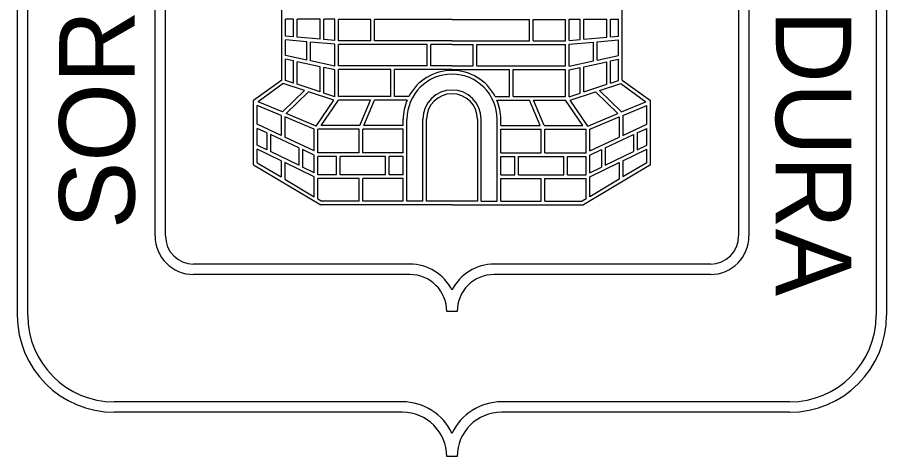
# Model space of a CAD drawing. Extents: x 0.2 to 61.3, y -17.9 to -0.8.
# Drawn here: x 33.86 to 43.86, y -17.88 to -12.82 of the extents above; entities that cross this region are included whole.
import ezdxf

# ---------------------------------------------------------------- set-up
doc = ezdxf.new("R2010")
doc.units = 0
doc.layers.add('Nivel 1', color=7, linetype='Continuous')
doc.layers.add('texto', color=7, linetype='Continuous')

msp = doc.modelspace()

# ---------------------------------------------------------------- linework, layer by layer
at = {"layer": 'Nivel 1'}
for p, q in [((33.86, -16.25), (33.86, -5.551)), ((43.86, -5.551), (43.86, -16.25)), ((33.979, -16.25), (33.979, -5.67)), ((43.741, -5.67), (43.741, -16.25)), ((35.444, -15.338), (35.444, -7.135)), ((42.276, -7.135), (42.276, -15.338)), ((35.563, -15.338), (35.563, -7.254)), ((42.157, -7.254), (42.157, -15.338)), ((36.901, -13.544), (36.901, -11.965)), ((40.819, -13.544), (40.819, -11.965)), ((37.035, -12.844), (36.943, -12.844)), ((36.943, -13.04), (36.943, -12.844)), ((37.035, -13.048), (37.035, -12.844)), ((37.342, -12.844), (37.077, -12.844)), ((37.077, -13.052), (37.077, -12.844)), ((37.342, -13.075), (37.342, -12.844)), ((37.512, -12.844), (37.385, -12.844)), ((37.385, -13.079), (37.385, -12.844)), ((37.512, -13.09), (37.512, -12.844)), ((37.927, -12.846), (37.554, -12.846)), ((37.554, -13.093), (37.554, -12.846)), ((37.927, -13.093), (37.927, -12.846)), ((38.86, -12.846), (37.97, -12.846)), ((37.97, -13.093), (37.97, -12.846)), ((38.86, -12.846), (39.75, -12.846)), ((39.75, -13.093), (39.75, -12.846)), ((39.792, -12.846), (40.165, -12.846)), ((39.792, -13.093), (39.792, -12.846)), ((40.165, -13.093), (40.165, -12.846)), ((40.208, -13.09), (40.208, -12.844)), ((40.208, -12.844), (40.335, -12.844)), ((40.335, -13.079), (40.335, -12.844)), ((40.377, -13.075), (40.377, -12.844)), ((40.377, -12.844), (40.642, -12.844)), ((40.642, -13.052), (40.642, -12.844)), ((40.685, -12.844), (40.776, -12.844)), ((40.685, -13.048), (40.685, -12.844)), ((40.776, -13.04), (40.776, -12.844)), ((37.035, -13.048), (36.943, -13.04)), ((36.943, -13.26), (36.943, -13.082)), ((37.191, -13.104), (36.943, -13.082)), ((37.342, -13.075), (37.077, -13.052)), ((37.512, -13.09), (37.385, -13.079)), ((37.927, -13.093), (37.554, -13.093)), ((38.86, -13.093), (37.97, -13.093)), ((38.86, -13.093), (39.75, -13.093)), ((39.792, -13.093), (40.165, -13.093)), ((40.208, -13.09), (40.335, -13.079)), ((40.377, -13.075), (40.642, -13.052)), ((40.529, -13.104), (40.776, -13.082)), ((40.685, -13.048), (40.776, -13.04)), ((40.776, -13.26), (40.776, -13.082)), ((37.191, -13.314), (37.191, -13.104)), ((37.233, -13.323), (37.233, -13.108)), ((37.512, -13.133), (37.233, -13.108)), ((37.512, -13.384), (37.512, -13.133)), ((38.576, -13.136), (37.554, -13.136)), ((37.554, -13.38), (37.554, -13.136)), ((38.576, -13.38), (38.576, -13.136)), ((38.86, -13.136), (38.618, -13.136)), ((38.618, -13.38), (38.618, -13.136)), ((38.86, -13.136), (39.102, -13.136)), ((39.102, -13.38), (39.102, -13.136)), ((39.144, -13.136), (40.165, -13.136)), ((39.144, -13.38), (39.144, -13.136)), ((40.165, -13.38), (40.165, -13.136)), ((40.208, -13.133), (40.486, -13.108)), ((40.208, -13.384), (40.208, -13.133)), ((40.486, -13.323), (40.486, -13.108)), ((40.529, -13.314), (40.529, -13.104)), ((37.191, -13.314), (36.943, -13.26)), ((40.529, -13.314), (40.776, -13.26)), ((37.035, -13.324), (36.943, -13.304)), ((36.943, -13.549), (36.943, -13.304)), ((37.035, -13.579), (37.035, -13.324)), ((37.342, -13.391), (37.077, -13.333)), ((37.077, -13.593), (37.077, -13.333)), ((37.512, -13.384), (37.233, -13.323)), ((37.342, -13.68), (37.342, -13.391)), ((37.512, -13.427), (37.385, -13.4)), ((37.385, -13.694), (37.385, -13.4)), ((38.576, -13.38), (37.554, -13.38)), ((38.86, -13.38), (38.618, -13.38)), ((38.86, -13.38), (39.102, -13.38)), ((39.144, -13.38), (40.165, -13.38)), ((40.208, -13.384), (40.486, -13.323)), ((40.208, -13.427), (40.335, -13.4)), ((40.335, -13.694), (40.335, -13.4)), ((40.377, -13.391), (40.642, -13.333)), ((40.377, -13.68), (40.377, -13.391)), ((40.642, -13.593), (40.642, -13.333)), ((40.685, -13.324), (40.776, -13.304)), ((40.685, -13.579), (40.685, -13.324)), ((40.776, -13.549), (40.776, -13.304)), ((37.512, -13.736), (37.512, -13.427)), ((38.157, -13.422), (37.554, -13.422)), ((37.554, -13.732), (37.554, -13.422)), ((38.157, -13.732), (38.157, -13.422)), ((38.86, -13.422), (38.2, -13.422)), ((38.2, -13.732), (38.2, -13.422)), ((38.86, -13.422), (39.52, -13.422)), ((39.52, -13.732), (39.52, -13.422)), ((39.562, -13.422), (40.165, -13.422)), ((39.562, -13.732), (39.562, -13.422)), ((40.165, -13.732), (40.165, -13.422)), ((40.208, -13.736), (40.208, -13.427)), ((36.901, -13.544), (36.577, -13.778)), ((36.917, -13.585), (36.628, -13.793)), ((37.163, -13.666), (36.917, -13.585)), ((37.035, -13.579), (36.943, -13.549)), ((37.342, -13.68), (37.077, -13.593)), ((40.377, -13.68), (40.642, -13.593)), ((40.556, -13.666), (40.803, -13.585)), ((40.685, -13.579), (40.776, -13.549)), ((40.803, -13.585), (41.091, -13.793)), ((40.819, -13.544), (41.142, -13.778)), ((36.909, -13.911), (37.163, -13.666)), ((36.951, -13.929), (37.209, -13.681)), ((37.501, -13.777), (37.209, -13.681)), ((37.512, -13.736), (37.385, -13.694)), ((40.208, -13.736), (40.335, -13.694)), ((40.219, -13.777), (40.511, -13.681)), ((40.768, -13.929), (40.511, -13.681)), ((40.811, -13.911), (40.556, -13.666)), ((36.577, -14.519), (36.577, -13.778)), ((36.909, -13.911), (36.628, -13.793)), ((37.298, -14.075), (37.501, -13.777)), ((37.355, -14.066), (37.554, -13.775)), ((38.157, -13.732), (37.554, -13.732)), ((37.922, -13.775), (37.554, -13.775)), ((37.799, -14.066), (37.922, -13.775)), ((37.845, -14.066), (37.968, -13.775)), ((38.344, -13.775), (37.968, -13.775)), ((38.364, -13.732), (38.2, -13.732)), ((39.356, -13.732), (39.52, -13.732)), ((39.376, -13.775), (39.752, -13.775)), ((39.562, -13.732), (40.165, -13.732)), ((39.875, -14.066), (39.752, -13.775)), ((39.921, -14.066), (39.798, -13.775)), ((39.798, -13.775), (40.165, -13.775)), ((40.364, -14.066), (40.165, -13.775)), ((40.422, -14.075), (40.219, -13.777)), ((40.811, -13.911), (41.091, -13.793)), ((41.142, -14.519), (41.142, -13.778)), ((36.62, -14.052), (36.62, -13.836)), ((36.895, -13.952), (36.62, -13.836)), ((40.825, -13.952), (41.1, -13.836)), ((41.1, -14.052), (41.1, -13.836)), ((36.895, -13.952), (36.895, -14.181)), ((36.938, -13.969), (36.938, -14.201)), ((37.275, -14.111), (36.938, -13.969)), ((37.298, -14.075), (36.951, -13.929)), ((38.299, -14.066), (38.299, -13.994)), ((38.342, -14.937), (38.342, -13.994)), ((38.524, -14.937), (38.524, -13.994)), ((39.195, -14.937), (39.195, -13.994)), ((39.378, -14.937), (39.378, -13.994)), ((39.42, -14.066), (39.42, -13.994)), ((40.422, -14.075), (40.768, -13.929)), ((40.444, -14.111), (40.782, -13.969)), ((40.782, -13.969), (40.782, -14.201)), ((40.825, -13.952), (40.825, -14.181)), ((36.895, -14.181), (36.62, -14.052)), ((36.62, -14.294), (36.62, -14.1)), ((36.729, -14.151), (36.62, -14.1)), ((37.799, -14.066), (37.355, -14.066)), ((38.299, -14.066), (37.845, -14.066)), ((39.42, -14.066), (39.875, -14.066)), ((39.921, -14.066), (40.364, -14.066)), ((40.825, -14.181), (41.1, -14.052)), ((40.99, -14.151), (41.1, -14.1)), ((41.1, -14.294), (41.1, -14.1)), ((36.729, -14.151), (36.729, -14.346)), ((36.772, -14.171), (36.772, -14.367)), ((37.097, -14.323), (36.772, -14.171)), ((37.275, -14.36), (37.275, -14.111)), ((37.791, -14.109), (37.318, -14.109)), ((37.318, -14.38), (37.318, -14.109)), ((37.791, -14.38), (37.791, -14.109)), ((38.299, -14.109), (37.834, -14.109)), ((37.834, -14.38), (37.834, -14.109)), ((38.299, -14.38), (38.299, -14.109)), ((39.42, -14.109), (39.886, -14.109)), ((39.42, -14.38), (39.42, -14.109)), ((39.886, -14.38), (39.886, -14.109)), ((39.928, -14.109), (40.402, -14.109)), ((39.928, -14.38), (39.928, -14.109)), ((40.402, -14.38), (40.402, -14.109)), ((40.444, -14.36), (40.444, -14.111)), ((40.623, -14.323), (40.948, -14.171)), ((40.948, -14.171), (40.948, -14.367)), ((40.99, -14.151), (40.99, -14.346)), ((36.729, -14.346), (36.62, -14.294)), ((37.275, -14.36), (36.938, -14.201)), ((40.444, -14.36), (40.782, -14.201)), ((40.99, -14.346), (41.1, -14.294)), ((36.62, -14.495), (36.62, -14.341)), ((36.893, -14.473), (36.62, -14.341)), ((37.097, -14.524), (36.772, -14.367)), ((37.097, -14.323), (37.097, -14.524)), ((37.139, -14.343), (37.139, -14.545)), ((37.275, -14.407), (37.139, -14.343)), ((37.791, -14.38), (37.318, -14.38)), ((38.299, -14.38), (37.834, -14.38)), ((39.42, -14.38), (39.886, -14.38)), ((39.928, -14.38), (40.402, -14.38)), ((40.444, -14.407), (40.58, -14.343)), ((40.58, -14.343), (40.58, -14.545)), ((40.623, -14.323), (40.623, -14.524)), ((40.623, -14.524), (40.948, -14.367)), ((40.826, -14.473), (41.1, -14.341)), ((41.1, -14.495), (41.1, -14.341)), ((36.62, -14.495), (36.893, -14.658)), ((36.893, -14.473), (36.893, -14.658)), ((36.936, -14.494), (36.936, -14.683)), ((37.275, -14.658), (36.936, -14.494)), ((37.275, -14.61), (37.275, -14.407)), ((37.531, -14.422), (37.318, -14.422)), ((37.318, -14.636), (37.318, -14.422)), ((37.531, -14.636), (37.531, -14.422)), ((37.574, -14.636), (37.574, -14.422)), ((38.094, -14.422), (37.574, -14.422)), ((38.094, -14.636), (38.094, -14.422)), ((38.137, -14.636), (38.137, -14.422)), ((38.299, -14.422), (38.137, -14.422)), ((38.299, -14.636), (38.299, -14.422)), ((39.42, -14.636), (39.42, -14.422)), ((39.42, -14.422), (39.583, -14.422)), ((39.583, -14.636), (39.583, -14.422)), ((39.625, -14.636), (39.625, -14.422)), ((39.625, -14.422), (40.146, -14.422)), ((40.146, -14.636), (40.146, -14.422)), ((40.188, -14.636), (40.188, -14.422)), ((40.188, -14.422), (40.402, -14.422)), ((40.402, -14.636), (40.402, -14.422)), ((40.444, -14.61), (40.444, -14.407)), ((40.444, -14.658), (40.784, -14.494)), ((40.784, -14.494), (40.784, -14.683)), ((40.826, -14.473), (40.826, -14.658)), ((41.1, -14.495), (40.826, -14.658)), ((36.577, -14.519), (37.349, -14.979)), ((37.275, -14.61), (37.139, -14.545)), ((41.142, -14.519), (40.371, -14.979)), ((40.444, -14.61), (40.58, -14.545)), ((36.936, -14.683), (37.275, -14.886)), ((37.275, -14.886), (37.275, -14.658)), ((37.531, -14.636), (37.318, -14.636)), ((37.791, -14.678), (37.318, -14.678)), ((37.318, -14.911), (37.318, -14.678)), ((38.094, -14.636), (37.574, -14.636)), ((37.791, -14.937), (37.791, -14.678)), ((38.299, -14.678), (37.834, -14.678)), ((37.834, -14.937), (37.834, -14.678)), ((38.299, -14.636), (38.137, -14.636)), ((38.299, -14.937), (38.299, -14.678)), ((39.42, -14.636), (39.583, -14.636)), ((39.42, -14.937), (39.42, -14.678)), ((39.42, -14.678), (39.886, -14.678)), ((39.625, -14.636), (40.146, -14.636)), ((39.886, -14.937), (39.886, -14.678)), ((39.928, -14.678), (40.402, -14.678)), ((39.928, -14.937), (39.928, -14.678)), ((40.188, -14.636), (40.402, -14.636)), ((40.402, -14.911), (40.402, -14.678)), ((40.444, -14.886), (40.444, -14.658)), ((40.784, -14.683), (40.444, -14.886)), ((37.318, -14.911), (37.361, -14.937)), ((38.86, -14.979), (37.349, -14.979)), ((37.791, -14.937), (37.361, -14.937)), ((38.299, -14.937), (37.834, -14.937)), ((38.524, -14.937), (38.342, -14.937)), ((38.86, -14.979), (40.371, -14.979)), ((39.195, -14.937), (39.378, -14.937)), ((39.42, -14.937), (39.886, -14.937)), ((39.928, -14.937), (40.359, -14.937)), ((40.402, -14.911), (40.359, -14.937)), ((38.374, -15.662), (35.887, -15.662)), ((41.833, -15.662), (39.345, -15.662)), ((38.374, -15.781), (35.887, -15.781)), ((41.833, -15.781), (39.345, -15.781)), ((38.86, -16.207), (38.8, -16.207)), ((38.919, -16.207), (38.86, -16.207)), ((38.289, -17.246), (34.975, -17.246)), ((42.744, -17.246), (39.43, -17.246)), ((38.289, -17.365), (34.975, -17.365)), ((42.744, -17.365), (39.43, -17.365)), ((38.86, -17.876), (38.8, -17.876)), ((38.919, -17.876), (38.86, -17.876))]:
    msp.add_line(p, q, dxfattribs=at)
for centre, radius, start, end in [((38.86, -13.994), 0.518, 90, 180), ((38.86, -13.994), 0.561, 90, 152.1822), ((38.86, -13.994), 0.561, 27.8178, 90), ((38.86, -13.994), 0.518, 0, 90), ((38.86, -13.994), 0.335, 90, 180), ((38.86, -13.994), 0.335, 0, 90), ((38.86, -13.994), 0.561, 157.0009, 180), ((38.86, -13.994), 0.561, 0, 22.9991), ((35.887, -15.338), 0.443, 180, 270), ((35.887, -15.338), 0.324, 180, 270), ((41.833, -15.338), 0.443, 270, 0), ((41.833, -15.338), 0.324, 270, 0), ((38.374, -16.207), 0.545, 27.0481, 90), ((39.345, -16.207), 0.545, 90, 152.9519), ((38.374, -16.207), 0.426, 0, 90), ((39.345, -16.207), 0.426, 90, 180), ((34.975, -16.25), 1.116, 180, 270), ((34.975, -16.25), 0.996, 180, 270), ((42.744, -16.25), 1.116, 270, 0), ((42.744, -16.25), 0.996, 270, 0), ((38.289, -17.876), 0.63, 25.1221, 90), ((39.43, -17.876), 0.63, 90, 154.8779), ((38.289, -17.876), 0.511, 0, 90), ((39.43, -17.876), 0.511, 90, 180)]:
    msp.add_arc(centre, radius, start, end, dxfattribs=at)
at = {"layer": 'texto'}
for p, q in [((38.567, -14.937), (38.567, -13.994)), ((39.153, -13.994), (39.153, -14.937)), ((38.86, -14.937), (38.567, -14.937)), ((39.153, -14.937), (38.86, -14.937))]:
    msp.add_line(p, q, dxfattribs=at)
for start, end in [(90, 180), (0, 90)]:
    msp.add_arc((38.86, -13.994), 0.293, start, end, dxfattribs=at)

# ---------------------------------------------------------------- texts
at = {"layer": 'Nivel 1'}
for s, height, rotation, p in [('ESTREMADURA ', 0.86862, 270, (42.585, -7.123)), ('SORIA', 0.8686, 90, (35.209, -15.258))]:
    msp.add_text(s, height=height, rotation=rotation, dxfattribs=at).set_placement(p)

doc.saveas('drawing.dxf')
